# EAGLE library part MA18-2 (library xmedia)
PIN HEADER
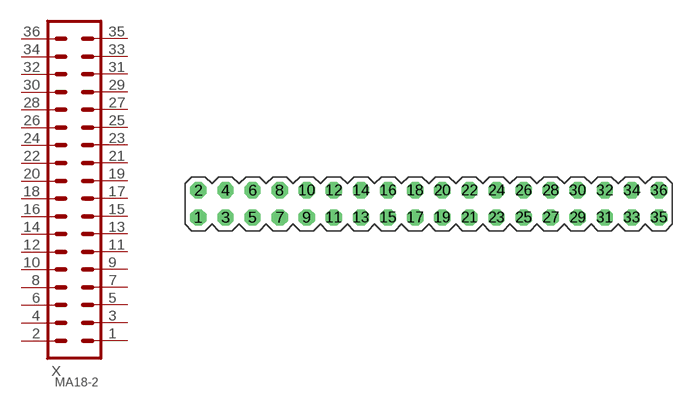
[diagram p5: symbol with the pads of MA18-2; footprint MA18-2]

Designator prefix X

## MA18-2  [MA18-2]
1  1  pas
2  2  pas
3  3  pas
4  4  pas
5  5  pas
6  6  pas
7  7  pas
8  8  pas
9  9  pas
10  10  pas
11  11  pas
12  12  pas
13  13  pas
14  14  pas
15  15  pas
16  16  pas
17  17  pas
18  18  pas
19  19  pas
20  20  pas
21  21  pas
22  22  pas
23  23  pas
24  24  pas
25  25  pas
26  26  pas
27  27  pas
28  28  pas
29  29  pas
30  30  pas
31  31  pas
32  32  pas
33  33  pas
34  34  pas
35  35  pas
36  36  pas

## Footprint MA18-2 (pad centres in mm)
PIN HEADER
drill 1.016 octagon: 1 -21.59,-1.27; 2 -21.59,1.27; 3 -19.05,-1.27; 4 -19.05,1.27; 5 -16.51,-1.27; 6 -16.51,1.27; 7 -13.97,-1.27; 8 -13.97,1.27; 9 -11.43,-1.27; 10 -11.43,1.27; 11 -8.89,-1.27; 12 -8.89,1.27; 13 -6.35,-1.27; 14 -6.35,1.27; 15 -3.81,-1.27; 16 -3.81,1.27; 17 -1.27,-1.27; 18 -1.27,1.27; 19 1.27,-1.27; 20 1.27,1.27; 21 3.81,-1.27; 22 3.81,1.27; 23 6.35,-1.27; 24 6.35,1.27; 25 8.89,-1.27; 26 8.89,1.27; 27 11.43,-1.27; 28 11.43,1.27; 29 13.97,-1.27; 30 13.97,1.27; 31 16.51,-1.27; 32 16.51,1.27; 33 19.05,-1.27; 34 19.05,1.27; 35 21.59,-1.27; 36 21.59,1.27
